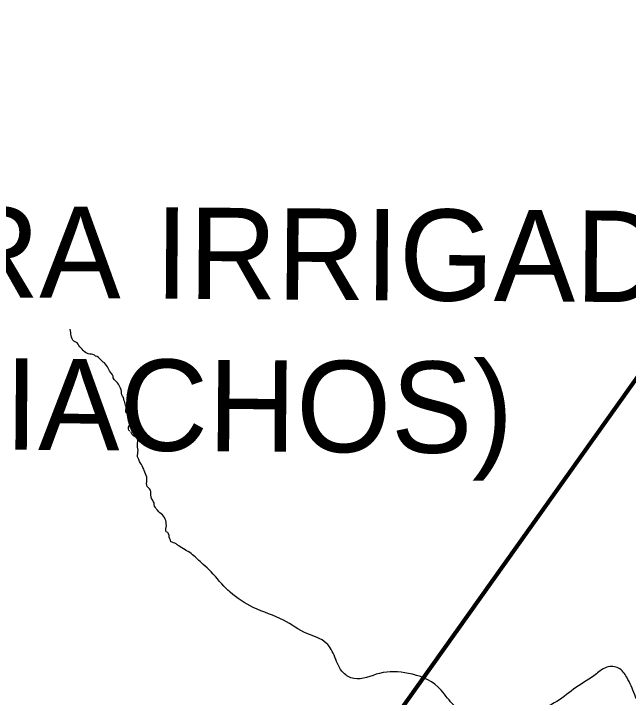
# Model space of a CAD drawing. Extents: x -1643653 to 4543381, y 1624270 to 13878484.
# Drawn here: x 704507 to 709556, y 8962130 to 8967746 of the extents above; entities that cross this region are included whole.
import ezdxf
from ezdxf.enums import TextEntityAlignment as Align

# ---------------------------------------------------------------- set-up
doc = ezdxf.new("R2010")
doc.units = 0
doc.header["$LTSCALE"] = 200
for name, color, linetype, lineweight in [('24', 7, 'Continuous', 25), ('26', 7, 'Continuous', 106), ('28', 7, 'Continuous', 53), ('60', 7, 'Continuous', 13), ('9', 7, 'Continuous', 90)]:
    doc.layers.add(name, color=color, linetype=linetype, lineweight=lineweight)
doc.layers.add('42', color=7, linetype='Continuous')

msp = doc.modelspace()

# ---------------------------------------------------------------- linework, layer by layer
at = {"layer": '24'}
for points in [[(705462, 8964317), (705454, 8964323.8), (705449.7, 8964336.7), (705451.5, 8964350), (705458.7, 8964361.9), (705468.1, 8964370.6), (705473.4, 8964382.4), (705470.6, 8964396.2), (705466.6, 8964409.2), (705463.8, 8964422), (705458.7, 8964433.7), (705454.1, 8964445.5), (705446.7, 8964456.5), (705436.3, 8964463.7), (705427.9, 8964475.5), (705427.5, 8964488.9), (705430.3, 8964502), (705430.9, 8964516), (705426.8, 8964529), (705424.1, 8964541.7), (705419.9, 8964553.7), (705415.7, 8964565.5), (705411.4, 8964578.6), (705408.1, 8964592.5), (705401.5, 8964603.7), (705395.9, 8964616.2), (705392.6, 8964629.3), (705391.6, 8964643), (705390.5, 8964656.5), (705385.8, 8964668.8), (705380.1, 8964681.2), (705374, 8964692.3), (705367.4, 8964703.5), (705359.7, 8964714.5), (705350.4, 8964723.6), (705340.7, 8964731.8), (705331.4, 8964740.9), (705324.3, 8964754.5), (705324.1, 8964767.8), (705318.9, 8964779.2), (705311.5, 8964790.4), (705302.1, 8964801.5), (705294.8, 8964811.6), (705289.5, 8964823), (705282.6, 8964834.3), (705277.5, 8964846), (705270.7, 8964857.2), (705262.2, 8964867.1), (705252.3, 8964876.4), (705240.9, 8964883.8), (705231.1, 8964892.9), (705222.1, 8964902.5), (705213.5, 8964912.7), (705203.7, 8964921.9), (705193.6, 8964930.3), (705180.4, 8964933.5), (705169.9, 8964940.5), (705158.2, 8964945), (705145.8, 8964948.7), (705132.4, 8964948.5), (705119.9, 8964950.6), (705108.2, 8964956.4), (705096.8, 8964963.6), (705087, 8964971.5), (705077.6, 8964979.9), (705068.8, 8964989.5), (705059.7, 8964999.7), (705050, 8965008.9), (705041.6, 8965019.5), (705036.2, 8965031.3), (705028.3, 8965041.6), (705016.9, 8965048.5), (705002.3, 8965055.8), (704992.8, 8965064.7), (704987, 8965075.9), (704982.4, 8965089.2), (704979.4, 8965101.5), (704977.2, 8965114.3), (704976.5, 8965127.2), (704973.7, 8965140.4), (704971.5, 8965153.2)], [(705796.9, 8963407.8), (705795.2, 8963421.2), (705789.1, 8963433), (705785.2, 8963445.2), (705783.8, 8963459), (705780, 8963472), (705772.6, 8963483.1), (705760.6, 8963488.6), (705755.9, 8963500.6), (705757.4, 8963514.6), (705760.4, 8963528.5), (705761.4, 8963541.1), (705760.8, 8963554.2), (705759.6, 8963568.1), (705757, 8963581.3), (705752.5, 8963594.8), (705746.6, 8963607), (705738.4, 8963618.3), (705729.5, 8963628), (705719.6, 8963636.3), (705708.3, 8963645.6), (705699.3, 8963655.2), (705688, 8963668.5), (705678.7, 8963678.5), (705670.9, 8963689.6), (705664.2, 8963701.2), (705661.4, 8963714.8), (705660.1, 8963727.5), (705654.2, 8963738.9), (705646.7, 8963751.8), (705640.5, 8963763.2), (705636.3, 8963775.9), (705634.8, 8963790.6), (705634.1, 8963803.8), (705632.8, 8963816.8), (705630.1, 8963830.7), (705623.7, 8963841.5), (705613.4, 8963851), (705604.1, 8963861.6), (705599.9, 8963874.2), (705599.2, 8963887.2), (705599.7, 8963900.5), (705601, 8963913.1), (705601.7, 8963926), (705599.6, 8963938.6), (705595.6, 8963951.5), (705590.5, 8963965.1), (705583.9, 8963980.3), (705579.5, 8963992.5), (705575.1, 8964004.7), (705569.2, 8964017.7), (705563.2, 8964031.1), (705556.4, 8964042.2), (705548.9, 8964054.6), (705541.1, 8964066.9), (705534.2, 8964082.5), (705529.1, 8964094.5), (705524.9, 8964106.6), (705524.7, 8964120.3), (705525.7, 8964132.8), (705527.2, 8964145.2), (705528.9, 8964158.3), (705528.4, 8964172.5), (705524.4, 8964184.8), (705523.4, 8964198.4), (705523.4, 8964204.9), (705525.6, 8964217.9), (705528, 8964230.7), (705526, 8964243.7), (705520.9, 8964255.5), (705512.5, 8964265), (705501.2, 8964271.4), (705490.1, 8964278.3), (705480.6, 8964288), (705474.5, 8964299), (705470.1, 8964311.2)]]:
    msp.add_lwpolyline(points, dxfattribs=at)
msp.add_spline([(710131.8, 8961656.3), (710038.2, 8961644.6), (709952.5, 8961734.3), (709819.9, 8961831.8), (709687.4, 8961917.5), (709656.2, 8962018.9), (709609.4, 8962151.4), (709543.1, 8962295.7), (709476.8, 8962369.8), (709379.4, 8962377.6), (709293.6, 8962323), (709126, 8962209.9), (708970, 8962096.9), (708782.9, 8962007.2), (708568.5, 8961929.2), (708381.3, 8961917.5), (708221.5, 8961987.7), (708096.8, 8962093), (707991.5, 8962217.7), (707749.8, 8962326.9), (707512, 8962326.9), (707301.5, 8962284), (707215.7, 8962330.8), (707145.5, 8962459.4), (707075.3, 8962576.4), (706915.5, 8962654.3), (706724.5, 8962763.5), (706475, 8962868.8), (706285.5, 8962993.6), (706252.3, 8963024.5), (706110.5, 8963180), (706048.8, 8963234.9), (705965.3, 8963310.3), (705863.5, 8963374.4), (705840.7, 8963390.4), (705796.9, 8963407.8)], degree=3, dxfattribs=at)
at = {"layer": '26'}
for points in [[(676174.9, 8960921), (676589.7, 8959851), (677298.5, 8959085), (677905.7, 8958370.4), (678108.1, 8958127.9), (678628.8, 8957871.5), (679175.3, 8957678.5), (679634.1, 8957740.2), (680271.7, 8957890.1), (680680.6, 8958130.1), (682556.7, 8958821.8), (683435.7, 8958881.7), (684580.7, 8958673.6), (685598.3, 8958453.2), (686374.5, 8958348.3), (687212.1, 8957836.1), (687682.2, 8957630.7), (688306.1, 8957615.5), (689591.9, 8957533.9), (690585.7, 8957606.1), (691389.1, 8957793.5), (691759.3, 8957957.3), (692919.9, 8958245), (693572, 8958700.2), (694136.4, 8959422.7), (694705.3, 8960908.2), (694927.7, 8961937.4), (695327.4, 8962800.5), (695494.2, 8963028.7), (696954.2, 8966672.4), (698159, 8968028.2), (699003.1, 8968647.8), (699373.7, 8968875.2), (699705.8, 8969051.9), (700930.8, 8969479.2), (701631.8, 8969565.3), (702395, 8969409.6), (703157, 8969037.7), (703804.2, 8968640.8), (704732, 8968306.3), (704974.2, 8968343.5), (705432.6, 8968328.9), (706400.3, 8968312.2), (707482.9, 8968320.5), (708005.4, 8968381.9), (708718.3, 8968340.8), (709660.3, 8968260.6), (710627.7, 8968180.3), (711187.5, 8968089), (711873, 8967704.7), (712851.5, 8967319.2), (713361.3, 8967393.4), (714238.5, 8967122.7), (715674, 8966506.4), (716373.4, 8966312.8), (717313.4, 8965902), (718673.1, 8965375), (719658.3, 8965140.1)], [(691088.7, 8957705.7), (691389.1, 8957793.5), (691759.3, 8957957.3), (692919.9, 8958245), (693572, 8958700.2), (694136.4, 8959422.7), (694705.3, 8960908.2), (694927.7, 8961937.4), (695327.4, 8962800.5), (695494.2, 8963028.7), (696954.2, 8966672.4), (698159, 8968028.2), (699003.1, 8968647.8), (699373.7, 8968875.2), (699705.8, 8969051.9), (700930.8, 8969479.2), (701631.8, 8969565.3), (702395, 8969409.6), (703157, 8969037.7), (703804.2, 8968640.8), (704732, 8968306.3), (704974.2, 8968343.5), (705432.6, 8968328.9), (706400.3, 8968312.2), (707482.9, 8968320.5), (708005.4, 8968381.9), (708718.3, 8968340.8), (709660.3, 8968260.6), (710627.7, 8968180.3), (711187.5, 8968089), (711873, 8967704.7), (712851.5, 8967319.2), (713361.3, 8967393.4), (714238.5, 8967122.7), (715674, 8966506.4), (716373.4, 8966312.8), (717313.4, 8965902), (718673.1, 8965375), (719658.3, 8965140.1)]]:
    msp.add_spline(points, degree=3, dxfattribs=at)
at = {"layer": '28'}
msp.add_spline([(707482.9, 8968320.5), (706400.3, 8968312.2), (705432.6, 8968328.9), (704974.2, 8968343.5), (704732, 8968306.3), (703804.2, 8968640.8), (703157, 8969037.7), (702395, 8969409.6), (701631.8, 8969565.3), (700930.8, 8969479.2), (699705.8, 8969051.9), (699373.7, 8968875.2), (699003.1, 8968647.8), (698159, 8968028.2), (696954.2, 8966672.4), (695494.2, 8963028.7), (695327.4, 8962800.5), (694975.6, 8962075.5)], degree=3, dxfattribs=at)
at = {"layer": '60', "lineweight": 25}
msp.add_spline([(814781, 9009175.5), (814787.2, 9009173.4), (814796.9, 9009173.4), (814799.4, 9009172.4), (814805.1, 9009174.5), (814805.6, 9009176.5), (814811.7, 9009179.5), (814811.7, 9009179.5), (814801.5, 9009181), (814790.7, 9009181.5), (814784.1, 9009183.1), (814777.4, 9009185.1), (814778.4, 9009175.5)], degree=3, dxfattribs=at)
at = {"layer": '9'}
msp.add_lwpolyline([(691582, 8951218.7), (697371.2, 8956056), (705081.2, 8958366.8), (713138.6, 8969695)], dxfattribs=at)

# ---------------------------------------------------------------- texts
at = {"layer": '42'}
for s, p in [('FORRAGEIRA IRRIGADA', (704633.4, 8965413.2)), ('(DOIS RIACHOS)', (704624.1, 8964163.3))]:
    msp.add_text(s, height=750, rotation=359.575, dxfattribs=at).set_placement(p, align=Align.CENTER)

doc.saveas('drawing.dxf')
